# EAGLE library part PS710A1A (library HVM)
NEC OPTO RELAY
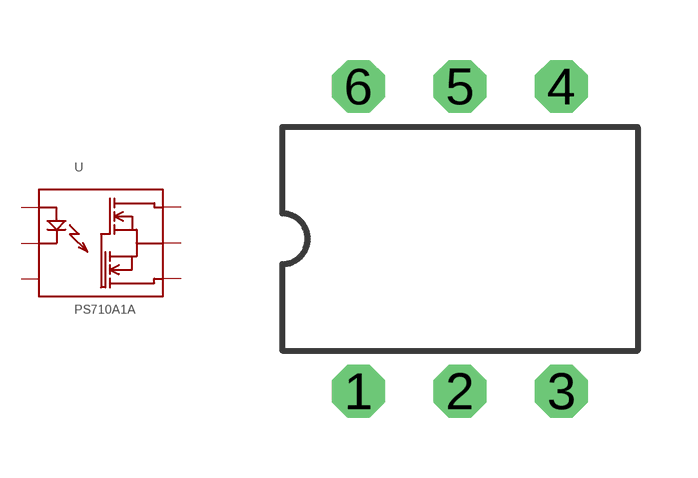
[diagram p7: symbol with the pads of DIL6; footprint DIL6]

Designator prefix U

## PS710A1A  [DIL6]
1  A  pas
2  C  pas
3  NC  nc
4  D1  pas
5  S  pas
6  D2  pas

## Footprint DIL6 (pad centres in mm)
drill 0.813 octagon: 1 -3.81,-3.81; 2 -1.27,-3.81; 3 1.27,-3.81; 4 1.27,3.81; 5 -1.27,3.81; 6 -3.81,3.81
